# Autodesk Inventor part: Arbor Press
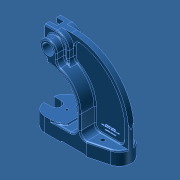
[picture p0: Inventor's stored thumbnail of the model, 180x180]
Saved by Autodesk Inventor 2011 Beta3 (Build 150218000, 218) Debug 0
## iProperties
Shininess: 64.0
Length Units: 11272
Angle Units: 11279
Time Units: 11290
Mass Units: 11286
Length Display Precision: 3
Angle Display Precision: 2
Compacted: True
Part Number: Arbor Press
Document SubType Name: Modeling
Created: 2003-11
Designer: Autodesk, Inc.
Manufacturer: Standard
Standards Organization: Custom
Mass: 6013.13 g
Surface Area: 1633.45 cm^2
Volume: 766.003 cm^3
Density: 7.85 g/cm^3
Material: Cast Steel
Density: 0.0
Volumn: 0.0
Area: 0.0
PropertySet Name: Model Information
Control State: 0
Master: False
Checked Out: False
Title: Arbor Press
Author: Autodesk, Inc.
Revision Number: A
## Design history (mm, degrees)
sketch "Sketch7"
  geometry: L1 (0, 0)-(0, 38.1); L2 (0, 38.1)-(79.375, 38.1); L3 (79.375, 38.1)-(79.375, 34.925); L4 (79.375, 34.925)-(117.475, 34.925); L5 (41.275, 165.1)-(11.201, 165.1); L6 (11.201, 165.1)-(11.201, 228.6); L7 (11.201, 228.6)-(66.675, 228.6); L8 (219.075, 76.2)-(219.075, 0); L9 (219.075, 0)-(141.275, 0); L10 (141.275, 0)-(0, 0); L11 (117.475, 34.925)-(117.475, 88.9); A1 r 152.4 centre (66.675, 76.2) between (219.075, 76.2) and (66.675, 228.6); A2 r 76.2 centre (41.275, 88.9) between (117.475, 88.9) and (41.275, 165.1)
  constraints: 22 end point, 8 parallel, 4 point on circle, 4 tangent, 2 centre point, 2 perpendicular, 1 collinear, 1 vertical
  dimensions: "d46" = 79.375 distance of L1.end L2.end; "d47" = 38.1 distance of L1.start L1.end; "d52" = 219.075 distance between parallel lines of L8 L1; "d53" = 228.6 distance between parallel lines of L10 L7; "d54" = 3.175 distance between parallel lines of L4 L2; "d55" = 152.4 radius of A1; "d56" = 76.2 radius of A2; "d57" = 63.5 distance of L5.end L6.end; "d59" = 25.4 horizontal distance of A1.centre A2.centre; "d60" = 30.0736 horizontal distance of A2.centre L5.end
extrude "Extrusion6" new body sketch "Sketch7" distance "d61" = 88.9; taper "d62" = 0 deg
sketch "Sketch8"
  geometry: L1 (207.874, 0)-(55.474, 0) reference; L2 (0, 0)-(55.474, 0) reference; L3 (-11.201, 0)-(68.174, 0) reference; L4 (-11.201, 0)-(-11.201, -88.9) reference; L5 (-11.201, -88.9)-(68.174, -88.9) reference; L6 (207.874, -88.9)-(55.474, -88.9) reference; L7 (207.874, 0)-(207.874, -88.9) reference; L8 (-11.201, -44.45)-(207.874, -44.45); L9 (-11.201, -44.45)-(-11.201, -33.325); L10 (22.123, 0)-(132.907, 0); L11 (132.907, 0)-(184.341, -13.782); L12 (22.123, -88.9)-(132.907, -88.9); L13 (132.907, -88.9)-(184.341, -75.118); L14 (-11.201, -44.45)-(-11.201, -55.575); A1 r 33.325 centre (22.123, -33.325) between (22.123, 0) and (-11.201, -33.325); A2 r 31.75 centre (176.124, -44.45) between (207.874, -44.45) and (184.341, -13.782); A3 r 33.325 centre (22.123, -55.575) between (-11.201, -55.575) and (22.123, -88.9); A4 r 31.75 centre (176.124, -44.45) between (184.341, -75.118) and (207.874, -44.45)
  constraints: 14 end point, 8 point on circle, 5 symmetric about line, 4 centre point, 4 point on line, 4 tangent, 2 midpoint, 1 collinear, 4 other
  dimensions: "d63" = 15 deg angle of L1 L11; "d64" = 33.3248 radius of A1; "d65" = 31.75 radius of A2
extrude "Extrusion7" sketch "Sketch8" stored distance "d66" = 88.9; taper "d67" = 0 deg
sketch "Sketch9"
  geometry: L1 (141.275, 3.175)-(76.2, 3.175) reference; L2 (144.108, 0)-(195.543, 0) reference; L3 (79.375, 34.925)-(117.475, 34.925) reference; L4 (117.475, 34.925)-(117.475, 88.9) reference; L5 (219.075, 34.925)-(127, 34.925); L6 (219.075, 76.2)-(219.075, 0) reference; L7 (11.201, 228.6)-(11.201, 165.1) reference; L8 (219.075, 34.925)-(219.075, 76.2); L9 (127, 88.9)-(127, 34.925); L10 (73.025, 228.6)-(73.025, 168.529); L11 (33.325, 228.6)-(66.675, 228.6) reference; A1 r 76.2 centre (41.275, 88.9) between (117.475, 88.9) and (41.275, 165.1) reference; A2 r 152.4 centre (66.675, 76.2) between (144.108, 207.463) and (66.675, 228.6) reference; A3 r 152.4 centre (66.675, 76.2) between (195.543, 157.557) and (144.108, 207.463) reference; A4 r 152.401 centre (66.674, 76.2) between (219.075, 76.2) and (195.543, 157.557); A5 r 152.4 centre (66.675, 76.2) between (195.543, 157.557) and (144.108, 207.463); A6 r 85.725 centre (41.275, 88.9) between (127, 88.9) and (73.025, 168.529); A7 r 152.4 centre (66.675, 76.2) between (144.108, 207.463) and (73.025, 228.468)
  constraints: 8 end point, 8 point on circle, 4 centre point, 3 concentric, 2 point on line, 1 collinear
  dimensions: "d86" = 9.525 distance between parallel lines of L9 L4; "d87" = 61.8236 distance between parallel lines of L10 L7; "d88" = 85.725 radius of A6; "d89" = 152.40105 radius of A4
workplane "Work Plane2"
extrude "Extrusion9" cut sketch "Sketch9" distance "d90" = 37.3126; taper "d91" = 0 deg
sketch "Sketch12"
  geometry: L1 (127, 34.925)-(127, 88.9) reference; L2 (144.108, 34.925)-(127, 34.925) reference; L3 (195.543, 34.925)-(144.108, 34.925) reference; L4 (195.543, 34.925)-(218.262, 34.925) reference; L5 (127, 88.9)-(127, 34.925); L6 (218.262, 91.917)-(218.262, 34.925) reference; L7 (208.737, 91.417)-(208.737, 34.925); L8 (66.212, 219.075)-(66.675, 219.075); L9 (208.737, 34.925)-(127, 34.925); L10 (73.025, 168.529)-(73.025, 218.934); L11 (73.025, 228.468)-(73.025, 228.6); A1 r 85.725 centre (41.275, 88.9) between (127, 88.9) and (73.025, 168.529) reference; A2 r 85.725 centre (41.275, 88.9) between (127, 88.9) and (73.025, 168.529); A3 r 152.4 centre (66.675, 76.2) between (195.543, 157.557) and (66.675, 228.6) reference; A4 r 152.401 centre (66.674, 76.2) between (218.262, 91.917) and (195.543, 157.557) reference; A5 r 142.875 centre (66.675, 76.2) between (187.488, 152.472) and (73.025, 218.934); A6 r 142.876 centre (66.674, 76.2) between (208.737, 91.417) and (187.488, 152.472); A7 r 85.725 centre (41.275, 88.9) between (127, 88.9) and (73.025, 168.529) reference; 2 further points; 1 other entity
  constraints: 12 end point, 9 point on circle, 3 centre point, 2 tangent, 1 collinear, 1 concentric, 1 point on line, 1 other
  dimensions: "d93" = 9.525 radial gap between concentric circles of A3 A5; "d94" = 9.525 distance between parallel lines of L6 L7; "d99" = 0 horizontal extent of L10; "d100" = 9.525 radial gap between concentric circles of A4 A6
extrude "Extrusion10" cut sketch "Sketch12" distance "d96" = 3.175; taper "d97" = 0 deg
sketch "Sketch13"
  geometry: L1 (33.325, 165.1)-(11.201, 165.1) reference; L2 (11.201, 228.6)-(11.201, 165.1) reference; L3 (11.201, 228.6)-(33.325, 228.6) reference; L4 (33.325, 228.6)-(66.675, 228.6) reference; L5 (41.275, 165.1)-(33.325, 165.1) reference; L6 (38.1, 165.1)-(38.1, 174.853); L7 (11.201, 196.85)-(77.125, 196.85); L8 (63.5, 196.85)-(63.5, 171.694); L9 (73.025, 168.529)-(73.025, 228.468) reference; L10 (38.1, 165.1)-(11.201, 165.1); L11 (11.201, 165.1)-(11.201, 228.6); L12 (73.025, 228.468)-(73.025, 168.529); L13 (12.066, 228.6)-(66.675, 228.6); A1 r 76.2 centre (41.275, 88.9) between (117.475, 88.9) and (41.275, 165.1) reference; A2 r 152.4 centre (66.675, 76.2) between (73.025, 228.468) and (66.675, 228.6) reference; A3 r 22.225 centre (41.275, 196.85) between (63.5, 196.85) and (38.1, 174.853); A4 r 85.725 centre (41.275, 88.9) between (127, 88.9) and (73.025, 168.529) reference; A5 r 85.725 centre (41.275, 88.9) between (73.025, 168.529) and (63.5, 171.694); A6 r 152.4 centre (66.675, 76.2) between (73.025, 228.468) and (66.675, 228.6)
  constraints: 14 end point, 6 point on circle, 4 perpendicular, 4 point on line, 3 centre point, 3 collinear, 2 concentric, 2 tangent, 1 midpoint
  dimensions: "d101" = 44.45 diameter of A3; "d102" = 30.0736 distance from line of L2 A3.centre; "d103" = 3.175 distance from line of A3.centre L6; "d105" = 9.525 radial gap between concentric circles of A1 A5
extrude "Extrusion11" cut sketch "Sketch13" distance "d106" = 22.225; taper "d107" = 0 deg
mirror "Mirror3"
sketch "Sketch14"
  geometry: L1 (0, 63.5)-(58.272, 63.5) reference; L2 (-8.403, 63.5)-(0, 63.5) reference; L3 (-8.403, 63.5)-(-8.403, 0) reference; L4 (0, 0)-(58.272, 0) reference; L5 (58.272, 0)-(58.272, 63.5) reference; L6 (58.272, 53.975)-(80.497, 53.975) reference; L7 (80.497, 52.504)-(80.497, 10.996) reference; L8 (80.497, 31.75)-(80.497, 53.975) reference; L9 (80.497, 9.753)-(80.497, 0) reference; L10 (80.497, 9.753)-(80.497, 10.996) reference; L11 (80.497, 0)-(58.272, 0) reference; L12 (13.822, 63.5)-(13.822, 9.525); L13 (13.822, 63.5)-(-8.403, 63.5); L14 (-8.403, 63.5)-(-8.403, 9.525); L15 (-8.403, 9.525)-(13.822, 9.525); L16 (0, 0)-(-8.403, 0) reference
  constraints: 8 end point, 3 perpendicular, 1 point on line
  dimensions: "d109" = 44.45 distance between parallel lines of L5 L12; "d111" = 9.525 distance between parallel lines of L4 L15
extrude "Extrusion12" cut sketch "Sketch14" stored distance "d112" = 22.225; taper "d113" = 0 deg
sketch "Sketch16"
  geometry: L1 (-33.325, 174.625)-(-73.025, 174.625) reference; L2 (-33.325, 174.625)-(-33.325, 165.1) reference; L3 (-73.025, 174.625)-(-73.025, 168.529) reference; L4 (-73.025, 168.529)-(-73.025, 174.625); L5 (-73.025, 174.625)-(-41.275, 174.625); A1 r 85.725 centre (-41.275, 88.9) between (-73.025, 168.529) and (-127, 88.9) reference; A2 r 85.725 centre (-41.275, 88.9) between (-41.275, 174.625) and (-73.025, 168.529)
  constraints: 4 end point, 2 collinear, 2 point on circle, 2 tangent, 1 centre point, 1 concentric, 1 point on line
extrude "Extrusion13" cut sketch "Sketch16" distance "d116" = 22.225; taper "d117" = 0 deg
workplane "Work Plane5"
sketch "Sketch17"
  geometry: L1 (11.201, 228.6)-(11.201, 174.625) reference; L2 (66.675, 228.6)-(11.201, 228.6) reference; L3 (73.025, 168.529)-(73.025, 228.468) reference; L4 (11.201, 215.9)-(41.275, 215.9); L5 (41.275, 177.8)-(11.201, 177.8); L6 (33.325, 165.1)-(11.201, 165.1) reference; A1 r 152.4 centre (66.675, 76.2) between (73.025, 228.468) and (66.675, 228.6) reference; A2 r 19.05 centre (41.275, 196.85) between (41.275, 177.8) and (41.275, 215.9)
  constraints: 4 end point, 2 point on circle, 2 point on line, 1 centre point, 1 parallel, 1 tangent
  dimensions: "d120" = 38.1 distance between parallel lines of L5 L4; "d121" = 19.05 radius of A2; "d122" = 12.7 distance of L1.start L4.start; "d123" = 12.7 distance of L6.end L5.end; "d124" = 30.0736 distance from line of L1 A2.centre
extrude "Extrusion14" cut sketch "Sketch17" stored distance "d125" = 25.4; taper "d126" = 0 deg
sketch "Sketch18"
  geometry: C1 r 14.879 at (41.275, 196.85); A1 r 22.225 centre (41.275, 196.85) between (63.5, 196.85) and (33.325, 217.604) reference
  constraints: 1 centre point, 1 coincident
  dimensions: "d127" = 29.758 diameter of C1
extrude "Extrusion15" cut sketch "Sketch18" distance "d128" = 38.1; taper "d129" = 0 deg
sketch "Sketch19"
  geometry: C1 r 9.538 at (41.275, 196.85); A1 r 22.225 centre (41.275, 196.85) between (63.5, 196.85) and (33.325, 217.604) reference; 2 further points
  constraints: 1 centre point, 1 coincident
  dimensions: "d130" = 19.0754 diameter of C1
extrude "Extrusion16" cut sketch "Sketch19" distance "d131" = 25.4; taper "d132" = 0 deg
fillet "Fillet2" dims "d134" = 15.875
fillet "Fillet3" dims "d135" = 15.875
sketch "Sketch20"
  geometry: L1 (11.201, 228.6)-(66.675, 228.6) reference; L2 (73.025, 228.468)-(73.025, 178.646) reference; L3 (41.275, 228.6)-(66.675, 228.6); L4 (73.025, 228.468)-(73.025, 196.85); C1 r 9.538 at (41.275, 196.85) reference; A1 r 31.75 centre (41.275, 196.85) between (73.025, 196.85) and (41.275, 228.6); A2 r 152.4 centre (66.675, 76.2) between (73.025, 228.468) and (66.675, 228.6) reference; A3 r 152.4 centre (66.675, 76.2) between (73.025, 228.468) and (66.675, 228.6)
  constraints: 4 end point, 4 point on circle, 2 centre point, 2 point on line, 2 tangent, 1 coincident, 1 collinear, 1 concentric
extrude "Extrusion17" cut sketch "Sketch20" distance "d136" = 15.0876; taper "d137" = 0 deg
mirror "Mirror4"
fillet "Fillet4" dims "d138" = 15.875
fillet "Fillet5" dims "d139" = 3.175
fillet "Fillet6" dims "d140" = 3.175
fillet "Fillet7" dims "d141" = 15.875
sketch "Sketch22"
  geometry: L1 (-79.375, 55.575)-(-79.375, 33.325) reference; L2 (-46.05, 0)-(0, 0) reference; L3 (-46.05, 88.9)-(0, 88.9) reference; L4 (-79.375, 44.45)-(-18.816, 44.45); L5 (-60.325, 57.944)-(-79.375, 57.944); L6 (-79.375, 30.956)-(-60.325, 30.956); L7 (-79.375, 57.944)-(-79.375, 30.956); A1 r 33.325 centre (-46.05, 55.575) between (-46.05, 88.9) and (-79.375, 55.575) reference; A2 r 33.325 centre (-46.05, 33.325) between (-79.375, 33.325) and (-46.05, 0) reference; A3 r 13.494 centre (-60.325, 44.45) between (-60.325, 30.956) and (-60.325, 57.944)
  constraints: 8 end point, 3 perpendicular, 3 point on line, 2 point on circle, 2 tangent, 1 centre point, 1 midpoint, 1 parallel
  dimensions: "d147" = 26.9875 diameter of A3; "d148" = 19.05 distance of L4.start A3.centre
extrude "Extrusion19" cut sketch "Sketch22" stored distance "d149" = 3.175; taper "d150" = 0 deg
sketch "Sketch23"
  geometry: L1 (0, 88.9)-(0, 0) reference; L2 (-46.05, 0)-(0, 0) reference; L3 (-60.325, 44.45)-(-10.181, 44.45); L4 (0, 13.341)-(0, 0); L5 (0, 0)-(-31.75, 0); A1 r 44.45 centre (-31.75, 44.45) between (-31.75, 0) and (0, 13.341); A2 r 13.494 centre (-60.325, 44.45) between (-60.325, 30.956) and (-60.325, 57.944) reference
  constraints: 6 end point, 3 point on line, 2 point on circle, 1 centre point, 1 parallel, 1 perpendicular
  dimensions: "d151" = 88.9 diameter of A1; "d153" = 28.575 distance of A1.centre L3.start
extrude "Extrusion20" cut sketch "Sketch23" distance "d154" = 3.175; taper "d155" = 0 deg
mirror "Mirror5"
fillet "Fillet10" dims "d157" = 15.875
fillet "Fillet11" dims "d158" = 15.875
fillet "Fillet12" dims "d159" = 15.875
fillet "Fillet15" dims "d162" = 15.875
sketch "Sketch24"
  geometry: L1 (-33.241, 57.944)-(-14.275, 57.944) reference; L2 (-14.275, 30.956)-(-33.241, 30.956) reference; L3 (110.783, 0)-(0, 0) reference; L4 (162.218, 13.782)-(110.783, 0) reference; L5 (110.783, 88.9)-(162.218, 75.118) reference; L6 (110.783, 88.9)-(0, 88.9) reference; L7 (0, 80.975)-(109.74, 80.975); L8 (109.74, 80.975)-(160.167, 67.463); L9 (160.167, 21.437)-(109.74, 7.925); L10 (109.74, 7.925)-(0, 7.925); L11 (-23.221, 23.031)-(-14.275, 23.031); L12 (-14.275, 65.869)-(-23.221, 65.869); A1 r 13.494 centre (-14.275, 44.45) between (-14.275, 30.956) and (-14.275, 57.944) reference; A2 r 33.325 centre (0, 33.325) between (-33.241, 30.956) and (0, 0) reference; A3 r 31.75 centre (154, 44.45) between (162.218, 13.782) and (162.218, 75.118) reference; A4 r 33.325 centre (0, 55.575) between (0, 88.9) and (-33.241, 57.944) reference; A5 r 23.825 centre (154, 44.45) between (160.167, 21.437) and (160.167, 67.463); A6 r 25.4 centre (0, 33.325) between (-23.221, 23.031) and (0, 7.925); A7 r 21.419 centre (-14.275, 44.45) between (-14.275, 23.031) and (-14.275, 65.869); A8 r 25.4 centre (0, 55.575) between (0, 80.975) and (-23.221, 65.869)
  constraints: 12 end point, 8 point on circle, 4 centre point, 9 other
  dimensions: "d163" = 7.9248 distance between parallel lines of L7 L6
extrude "Extrusion21" cut sketch "Sketch24" distance "d164" = 26.9875; taper "d165" = 0 deg
sketch "Sketch25"
  geometry: L1 (144.108, 0)-(33.325, 0) reference; L2 (33.325, 0)-(0.084, 0) reference; L3 (0.084, 38.1)-(0.084, 0) reference; L4 (76.284, 0)-(76.284, 3.175); L5 (76.284, 3.175)-(141.359, 3.175); L6 (141.359, 3.175)-(141.359, 0)
  constraints: 6 end point, 2 parallel, 2 point on line, 1 perpendicular
  dimensions: "d166" = 76.2 distance between parallel lines of L3 L4; "d167" = 65.0748 distance of L4.end L5.end; "d168" = 3.175 distance between parallel lines of L1 L5
extrude "Extrusion22" cut sketch "Sketch25" stored distance "d169" = 26.9875; taper "d170" = 0 deg
sketch "Sketch27"
  geometry: L1 (-23.221, 65.869)-(-14.275, 65.869) reference; L2 (-14.275, 23.031)-(-23.221, 23.031) reference; L3 (0, 7.925)-(109.74, 7.925) reference; L4 (109.74, 7.925)-(160.167, 21.437) reference; L5 (160.167, 67.463)-(109.74, 80.975) reference; L6 (109.74, 80.975)-(0, 80.975) reference; L7 (27, 80.975)-(27, 7.925); L8 (103.226, 80.975)-(103.226, 7.925); L9 (27, 80.975)-(103.226, 80.975); L10 (27, 7.925)-(103.226, 7.925); A1 r 25.4 centre (0, 55.575) between (0, 80.975) and (-23.221, 65.869) reference; A2 r 21.419 centre (-14.275, 44.45) between (-14.275, 23.031) and (-14.275, 65.869) reference; A3 r 25.4 centre (0, 33.325) between (-23.221, 23.031) and (0, 7.925) reference; A4 r 23.825 centre (154, 44.45) between (160.167, 21.437) and (160.167, 67.463) reference; A5 r 31.75 centre (154, 44.45) between (162.218, 13.782) and (162.218, 75.118) reference; 1 further point
  constraints: 8 end point, 4 point on line, 2 collinear, 2 perpendicular
  dimensions: "d176" = 60.325 distance from line of L7 point (-33.325, 0); "d178" = 50.7746 distance from line of A4.centre L8
extrude "Extrusion23" join sketch "Sketch27" distance "d179" = 12.6873; taper "d180" = 0 deg
workplane "Work Plane7"
sketch "Sketch28"
  geometry: L1 (-136.55, 14.3)-(-136.55, 26.988) reference; L2 (-60.325, 14.3)-(-136.55, 14.3) reference; L3 (-136.55, 26.988)-(-114.575, 14.3); L4 (-114.575, 14.3)-(-136.55, 14.3); L5 (-136.55, 14.3)-(-136.55, 26.988)
  constraints: 6 end point, 1 collinear, 1 perpendicular, 1 point on line
  dimensions: "d182" = 30 deg angle of L2 L3
extrude "Extrusion24" cut sketch "Sketch28" stored distance "d183" = 73.0504; taper "d184" = 0 deg
fillet "Fillet17" dims "d185" = 3.175
sketch "Sketch29"
  geometry: L1 (-58.272, 0)-(0, 0) reference; L2 (0, 0)-(0, 63.5) reference; L3 (-44.45, 63.5)-(0, 63.5) reference; L4 (-44.45, 63.5)-(-44.45, 9.525) reference; L5 (-58.272, 0)-(-58.272, 9.525) reference; L6 (-9.525, 50.8)-(-9.525, 12.7) reference; L7 (-9.525, 12.7)-(-34.925, 12.7) reference; L8 (-34.925, 12.7)-(-34.925, 50.8) reference; L9 (-34.925, 50.8)-(-9.525, 50.8) reference; L10 (-22.225, 63.5)-(-22.225, 0); L11 (-6.35, 57.15)-(-61.925, 57.15); L12 (-34.925, 31.75)-(-9.525, 31.75); L13 (-44.45, 9.525)-(-58.272, 9.525) reference; 3 further points
  constraints: 6 end point, 3 midpoint, 2 perpendicular, 2 point on line, 2 symmetric about line
  dimensions: "d186" = 31.75 distance of L11.start point (-38.1, 57.15); "d187" = 15.875 distance from line of L11.start L10; "d188" = 6.35 distance from line of L3 L11.start
hole "Hole1" sketch "Sketch29" at (-38.1, 57.15), (-6.35, 57.15), (-38.1, 6.35), (-6.35, 6.35) diameter "d189" = 4.9784; stored, may be unused: countersink angle "d193" = 82 deg, drill point angle "d195" = 118 deg; dims "d190" = 12.7, "d191" = 9.525, "d192" = 6.35, "d194" = 19.1008
sketch "Sketch30"
  geometry: L1 (-31.75, -49.954)-(-31.75, -31.75) reference; L2 (30.074, -53.975)-(0, -53.975) reference; L3 (30.074, 0)-(30.074, -53.975) reference; L4 (0, 0)-(30.074, 0) reference; L5 (20.549, -19.05)-(20.549, -44.45); L6 (30.074, -63.5)-(7.95, -63.5) reference; C1 r 9.538 at (0, -31.75) reference; A1 r 31.75 centre (0, -31.75) between (0, 0) and (-31.75, -31.75) reference; A2 r 15.875 centre (-47.625, -49.954) between (-40.184, -63.976) and (-31.75, -49.954) reference; A3 r 85.725 centre (0, -139.7) between (0, -53.975) and (-40.184, -63.976) reference; 1 further point
  constraints: 2 end point
  dimensions: "d196" = 25.4 distance of L5.start L5.end; "d197" = 9.525 distance from line of L3 L5.start; "d255" = 6.35 vertical distance of point (30.074, -50.8) L5.end; "d256" = 20.5486 horizontal distance of A1.centre L5.end
hole "Hole2" sketch "Sketch30" at (20.549, -19.05), (20.549, -44.45) diameter "d199" = 3.9624; stored, may be unused: countersink angle "d203" = 82 deg, drill point angle "d205" = 118 deg; dims "d200" = 12.7, "d201" = 9.525, "d202" = 6.35, "d204" = 19.05
sketch "Sketch31"
  geometry: C1 r 9.538 at (0, -31.75) reference; C2 r 17.45 at (0, -31.75)
  constraints: 1 centre point, 1 coincident
  dimensions: "d206" = 17.4498 radius of C2
extrude "Extrusion25" join sketch "Sketch31" distance "d207" = 9.525; taper "d208" = 0 deg
fillet "Fillet19" dims "d210" = 3.175
sketch "Sketch32"
  geometry: L1 (-42.85, 29.362)-(-42.85, 38.887) reference; L2 (-25.4, 38.887)-(-25.4, 5.475); L3 (-42.85, 38.887)-(-7.95, 38.887) reference; 1 further point
  constraints: 2 end point, 1 parallel, 1 point on line
  dimensions: "d290" = 4.7625 distance from line of L3 point (-25.4, 34.125)
hole "Hole3" sketch "Sketch32" at (-25.4, 34.125) diameter "d212" = 3.175; stored, may be unused: countersink angle "d216" = 82 deg, drill point angle "d218" = 118 deg; dims "d213" = 12.7, "d214" = 9.525, "d215" = 6.35, "d217" = 25.4
sketch "Sketch34"
  geometry: A1 r 13.494 centre (-173.812, 7.137) between (-173.812, -6.356) and (-173.812, 20.631) reference; 1 further point
  dimensions: "d228" = 142.875 horizontal distance of point (-30.937, -11.913) A1.centre; "d229" = 19.05 vertical distance of point (-30.937, -11.913) A1.centre
hole "Hole5" sketch "Sketch34" at (-30.937, -11.913) diameter "d230" = 10.3124; stored, may be unused: countersink angle "d234" = 82 deg, drill point angle "d236" = 118 deg; dims "d231" = 12.7, "d232" = 9.525, "d233" = 6.35, "d235" = 12.7
mirror "Mirror6"
sketch "Sketch35"
  geometry: A1 r 13.494 centre (18.966, -13.494) between (18.966, -26.988) and (18.966, 0) reference; 1 further point
  dimensions: "d237" = 28.575 distance of point (47.541, -13.494) A1.centre; "d238" = 0 vertical distance of A1.centre point (47.541, -13.494)
hole "Hole6" sketch "Sketch35" at (47.541, -13.494) diameter "d239" = 6.731; stored, may be unused: countersink angle "d243" = 82 deg, drill point angle "d245" = 118 deg; dims "d240" = 12.7, "d241" = 9.525, "d242" = 6.35, "d244" = 12.7
sketch "Sketch36"
  geometry: L1 (-58.272, 0)-(0, 0) reference; L2 (0, 0)-(0, 63.5) reference; L3 (-44.45, 63.5)-(0, 63.5) reference; L4 (-44.45, 63.5)-(-44.45, 9.525) reference; L5 (-58.272, 0)-(-58.272, 9.525) reference; L6 (-9.525, 50.8)-(-9.525, 12.7) reference; L7 (-9.525, 12.7)-(-34.925, 12.7) reference; L8 (-34.925, 12.7)-(-34.925, 50.8) reference; L9 (-34.925, 50.8)-(-9.525, 50.8) reference; L10 (-31.75, 63.5)-(-31.75, 50.8); L11 (-12.725, 63.5)-(-12.725, 50.8); L12 (-34.925, 31.75)-(-9.525, 31.75); L13 (-22.225, 50.8)-(-22.225, 31.75); L14 (-31.75, 63.5)-(-12.725, 63.5); L15 (-31.75, 50.8)-(-12.725, 50.8); L16 (-44.45, 9.525)-(-58.272, 9.525) reference; C1 r 2.489 at (-38.1, 6.35) reference; C2 r 2.489 at (-38.1, 57.15) reference; C3 r 2.489 at (-6.35, 57.15) reference; C4 r 2.489 at (-6.35, 6.35) reference
  constraints: 12 end point, 4 midpoint, 4 point on line, 3 perpendicular, 1 parallel
  dimensions: "d246" = 19.0246 distance between parallel lines of L11 L10; "d247" = 9.4996 distance between parallel lines of L11 L13
extrude "Extrusion26" cut sketch "Sketch36" distance "d248" = 19.1008; taper "d249" = 0 deg
workplane "Work Plane8"
mirror "Mirror7"
sketch "Sketch37"
  geometry: L1 (-11.201, 174.625)-(-41.275, 174.625) reference; L2 (-30.302, 165.1)-(-11.201, 165.1) reference; L3 (-11.201, 165.1)-(-11.201, 177.8) reference; L4 (-11.201, 174.625)-(-11.201, 165.1); L5 (-41.275, 174.625)-(-11.201, 174.625); L6 (-41.275, 174.625)-(-41.275, 165.1); L7 (-11.201, 165.1)-(-41.275, 165.1)
  constraints: 8 end point, 2 collinear, 2 perpendicular
extrude "Extrusion27" join sketch "Sketch37" distance "d251" = 12.7; taper "d252" = 0 deg
delete_face "Delete Face1"
sketch "Sketch39"
  geometry: L1 (180.803, 172.743)-(244.935, 172.743); L2 (244.935, 172.743)-(244.935, 72.014); L3 (244.935, 72.014)-(180.803, 72.014); L4 (180.803, 72.014)-(180.803, 172.743)
  constraints: 8 end point, 2 parallel, 1 horizontal, 1 perpendicular
extrude "Extrusion28" cut sketch "Sketch39" distance "d264" = 25.4; taper "d265" = 0 deg
mirror "Mirror8"
fillet "Fillet21" dims "d266" = 3.175
fillet "Fillet22" dims "d267" = 3.175
fillet "Fillet23" dims "d268" = 3.175
sketch "Sketch40"
  geometry: L1 (-3.175, -34.138)-(-30.956, -34.138) reference; L2 (-3.175, -34.138)-(-3.175, -18.263) reference; L3 (-30.956, -18.263)-(-3.175, -18.263) reference; L4 (-30.956, -34.138)-(-30.956, -18.263) reference; L5 (-47.625, -18.263)-(-47.625, -34.138) reference; L6 (-23.812, 34.125)-(-23.812, -34.138); L7 (-6.35, -37.313)-(-44.45, -37.313) reference; C1 r 1.587 at (-23.812, -26.213); 2 further points
  constraints: 2 end point, 2 point on line, 1 centre point, 1 perpendicular
  dimensions: "d272" = 3.175 diameter of C1; "d275" = 11.0998 distance from line of L7 C1.centre
extrude "Extrusion29" cut sketch "Sketch40" distance "d276" = 25.4; taper "d277" = 0 deg
sketch "Sketch41"
  geometry: L1 (22.225, 60.325)-(22.225, 9.525) reference; L2 (22.225, 9.525)-(0, 9.525) reference; L3 (0, 0)-(0, 9.525) reference; L4 (0, 0)-(34.925, 0) reference; L5 (34.925, 0)-(34.925, 12.7) reference; L6 (31.75, 12.7)-(31.75, 50.8) reference; L7 (34.925, 50.8)-(34.925, 63.5) reference; L8 (25.4, 63.5)-(34.925, 63.5) reference; L9 (22.225, 9.525)-(22.225, 0); L10 (22.225, 0)-(0, 0); L11 (0, 0)-(0, 9.525); L12 (0, 9.525)-(22.225, 9.525); L13 (34.925, 12.7)-(31.75, 12.7) reference; L14 (31.75, 50.8)-(34.925, 50.8) reference; C1 r 2.489 at (28.575, 57.15) reference; C2 r 2.489 at (28.575, 6.35) reference; A1 r 3.175 centre (25.4, 60.325) between (25.4, 63.5) and (22.225, 60.325) reference
  constraints: 8 end point, 2 collinear, 2 perpendicular, 1 point on line
extrude "Extrusion30" cut sketch "Sketch41" distance "d278" = 26.8986; taper "d279" = 0 deg
fillet "Fillet27" dims "d280" = 3.175
fillet "Fillet28" dims "d281" = 3.175
fillet "Fillet30" dims "d283" = 3.175
sketch "Sketch42"
  geometry: L1 (3.175, -31.75)-(3.175, -22.225) reference; L2 (-102.833, -196.85)-(-102.833, -165.1) reference; L3 (-102.833, -196.85)-(-100.084, -196.85) reference; L4 (-100.084, -193.675)-(-35.009, -193.675) reference; L5 (7.95, -158.75)-(7.95, -196.85) reference; L6 (7.95, -158.75)-(-6.35, -158.75) reference; L7 (3.175, -22.225)-(3.175, -17.159); L8 (-17.45, 0)-(-17.45, -24.02); L9 (0, -22.225)-(3.175, -22.225); L10 (-102.833, -165.1)-(-101.6, -165.1) reference; L11 (-82.55, -146.05)-(-82.55, -107.95) reference; L12 (-60.325, -165.1)-(-6.35, -165.1) reference; L13 (-79.375, -107.95)-(-79.375, -146.05) reference; L14 (3.175, -28.575)-(0, -28.575) reference; L15 (3.175, -28.575)-(3.175, -25.4) reference; L16 (0, -25.4)-(3.175, -25.4) reference; L17 (-100.084, -196.85)-(-100.084, -193.675) reference; L18 (-35.009, -193.675)-(-35.009, -196.85) reference; L19 (-35.009, -196.85)-(7.95, -196.85) reference; L20 (-6.35, -158.75)-(-6.35, -165.1) reference; A1 r 17.45 centre (0, 0) between (3.175, -17.159) and (-17.45, 0) reference; A2 r 17.45 centre (0, 0) between (-17.45, 0) and (3.175, -17.159); A3 r 85.725 centre (0, -107.95) between (0, -22.225) and (-17.45, -24.02); A4 r 82.55 centre (0, -107.95) between (0, -25.4) and (-82.55, -107.95) reference; A5 r 19.05 centre (-101.6, -146.05) between (-101.6, -165.1) and (-82.55, -146.05) reference; A6 r 19.05 centre (-60.325, -146.05) between (-79.375, -146.05) and (-60.325, -165.1) reference; A7 r 79.375 centre (0, -107.95) between (0, -28.575) and (-79.375, -107.95) reference
  constraints: 6 end point, 6 point on circle, 3 tangent, 2 centre point, 1 concentric, 1 parallel, 1 perpendicular
extrude "Extrusion31" join sketch "Sketch42" distance "d284" = 9.525; taper "d285" = 0 deg
fillet "Fillet31" dims "d286" = 3.175
fillet "Fillet32" dims "d287" = 3.175
fillet "Fillet33" dims "d288" = 3.175
fillet "Fillet34" dims "d289" = 3.175
sketch "Sketch43"
  geometry: L1 (123.521, 60.955)-(212.511, 60.955); L2 (212.511, 60.955)-(212.511, 48.209); L3 (212.511, 48.209)-(123.521, 48.209); L4 (123.521, 48.209)-(123.521, 60.955)
  constraints: 2 other
emboss "Emboss1" sketch "Sketch43" dims "d293" = 2.54, "d294" = 0
fillet "Fillet35" dims "d295" = 3.175
fillet "Fillet36" dims "d296" = 3.175
fillet "Fillet37" dims "d297" = 3.175
fillet "Fillet38" dims "d298" = 3.175
fillet "Fillet39" dims "d299" = 3.175
body "Solid1"
node "Projected Loop4"
node "Projected Loop5"
node "Projected Loop6"
node "Projected Loop7"
node "Projected Loop8"
node "Projected Loop9"
node "Projected Loop10"
node "Projected Loop11"
other parameters: "d32" = 47.625, "d33" = 47.625, "d39" = 47.625, "d76" = 61.8236, "d80" = -44.45, "d98" = 31.75, "d118" = -22.225, "d181" = -44.45, "d250" = -31.75
